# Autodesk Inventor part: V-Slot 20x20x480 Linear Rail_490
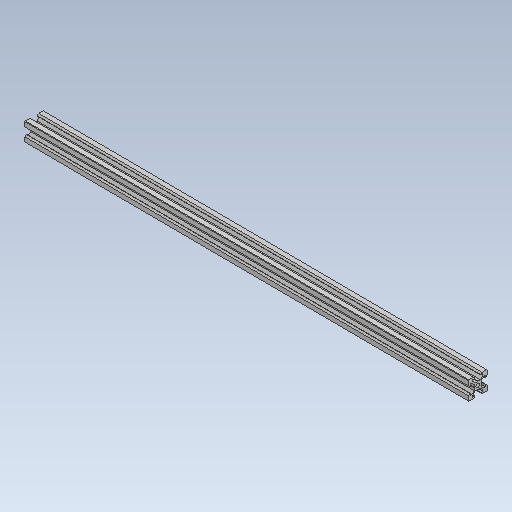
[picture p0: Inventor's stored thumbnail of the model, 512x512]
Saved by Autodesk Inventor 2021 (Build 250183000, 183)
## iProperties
Created: 2026-10
Part Number: V-Slot 20x20x480 Linear Rail_490
Material: Steel
Document SubType Name: Modeling
Designer: hp
Density: 7.85 g/cm^3
Appearance: Default
Author: hp
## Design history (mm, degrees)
feature "Body1"
body "Solid1"
